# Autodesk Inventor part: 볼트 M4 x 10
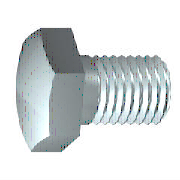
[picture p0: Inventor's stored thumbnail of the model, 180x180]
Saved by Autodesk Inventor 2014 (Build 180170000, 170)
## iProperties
Created: 2012-02
Part Number: 볼트 M4 x 10
Material: 스테인리스강
Description: 6각 머리 나사
Document SubType Name: Modeling
Standard: ISO 4017
Designer: mduedu
Standard Revision: Third edition 1999-08-15
Standards Organization: ISO
Language: ko-KR
Size Designation: M4 x 10
Categories: <MemberInstance><Categories><Category DisplayName="조임쇠" InternalName="e4da775c-781d-43d5-af7c-5136215cf5a6" Mnemonic="FSTN"><Category DisplayName="볼트" InternalN
Density: 8.08 g/cm^3
Appearance: Default
IsCustomPart: 0
Author: mduedu
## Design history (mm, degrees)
sketch "스케치1"
  geometry: L1 (0, 3.015)-(0, 2); L2 (2.1, 2)-(10, 2); L3 (10, 2)-(10, 0); L4 (10, 0)-(-0.4, 0); L5 (-2.48, 0)-(12.08, 0) reference; L6 (-0.4, 0)-(-0.4, 3.015); L7 (-0.4, 3.015)-(0, 3.015); L8 (2.1, 2)-(1.67, 2); L9 (1.67, 2)-(0, 2); L10 (0, -0.603)-(0, 3.618) reference
  constraints: 16 end point, 2 collinear, 2 perpendicular, 1 parallel
  dimensions: "d0" = 10 distance between parallel lines of L3 L1 (= NLG); "d1" = 7.9 distance from line of L2.start L3 (= GEL); "d2" = 4 diameter of L2 L4 (= GD); "d9" = 0.4001 distance between parallel lines of L6 L1 (computed from SD); "d10" = 6.03 diameter of L7 L4 (= SD2); "d13" = 0.42952 distance of L2.start L8.end (computed from GAL); "d14" = 4 diameter of L9 L4 (= BDM)
revolve "본체" sketch "스케치1" stored, may be unused: angle "d12" = 90 deg
sketch "스케치2"
  geometry: L1 (0, 4.041)-(3.5, 2.021); L2 (3.5, 2.021)-(3.5, -2.021); L3 (3.5, -2.021)-(0, -4.041); L4 (0, -4.041)-(-3.5, -2.021); L5 (-3.5, -2.021)-(-3.5, 2.021); L6 (-3.5, 2.021)-(0, 4.041); 2 further points
  constraints: 12 end point, 1 coincident, 1 vertical, 11 other
  dimensions: "d11" = 7 distance between parallel lines of L5 L2 (= SW)
extrude "머리" join sketch "스케치2" distance "d3" = 2.4 (= KOH - SD); taper "d4" = 0 deg
sketch "스케치4"
  geometry: L1 (-2.8, 3.5)-(-2.8, 4.041); L2 (-2.8, 4.041)-(-2.487, 4.041); L3 (-2.487, 4.041)-(-2.8, 3.5); L4 (-3.28, 0)-(0.08, 0) reference; L5 (-0.4, 4.041)-(-2.8, 4.041) reference; L6 (-2.8, 2.021)-(-2.8, 4.041) reference
  constraints: 6 end point, 2 collinear, 1 perpendicular, 1 vertical
  dimensions: "d5" = 30 deg angle of L3 L1 (= ANG1); "d19" = 7 diameter of L1.start L4 (= SW0)
revolve "모따기1" sketch "스케치4" stored, may be unused: angle "d21" = 90 deg
workplane "Work Plane1"
body "Solid1"
feature "스레드" dims "d15" = 7.9 (= GEL), "d16" = 0
chamfer "모따기2" distance "d6" = 0.42941 (= -0.5 x SPD + 0.5 x GD); stored, may be unused: second distance "d7" = 0.42952 (computed from GUL), angle "d55" = 45 deg
other parameters: "NLG" = 10 [user parameter; used in 1 equation term], "GD" = 4 (= NND) [user parameter; used in 2 equation terms], "BDM" = 4 (= NND) [user parameter; used in 1 equation term], "KOH" = 2.8 [user parameter; used in 1 equation term], "GEL" = 7.9 [user parameter; used in 2 equation terms], "SW" = 7 [user parameter; used in 2 equation terms], "SW0" = 7 (= SW) [user parameter; used in 1 equation term], "SPD" = 3.14117 (= NND - 1.2269 x PTC) [user parameter; used in 1 equation term], "SD2" = 6.03 [user parameter; used in 2 equation terms], "SD" = 0.4 [user parameter; used in 2 equation terms], "ANG1" = 30 deg [user parameter; used in 1 equation term], "GAL" = 0.42941 (= 0.61345 x PTC) [user parameter; used in 1 equation term], "GUL" = 0.42941 (= 0.61345 x PTC) [user parameter; used in 1 equation term], "d8" = 0, "RR" = 0.2 [user parameter], "d57" = 0, "d58" = 0, "TPU" = 14.28571 (computed from PTC) [user parameter], "GD1" = 3.14117 (= THREADDIA - 1.2269 x PTC) [user parameter], "THREADDIA" = 4 [user parameter; used in 1 equation term], "SDH" = 6.03 (= SD2) [user parameter], "SDHG" = 2.1 [user parameter], "TOA" = 30 deg [user parameter], "PTC" = 0.7 [user parameter; used in 5 equation terms], "NND" = 4 [user parameter; used in 3 equation terms], "E0" = 8.085 [user parameter]
